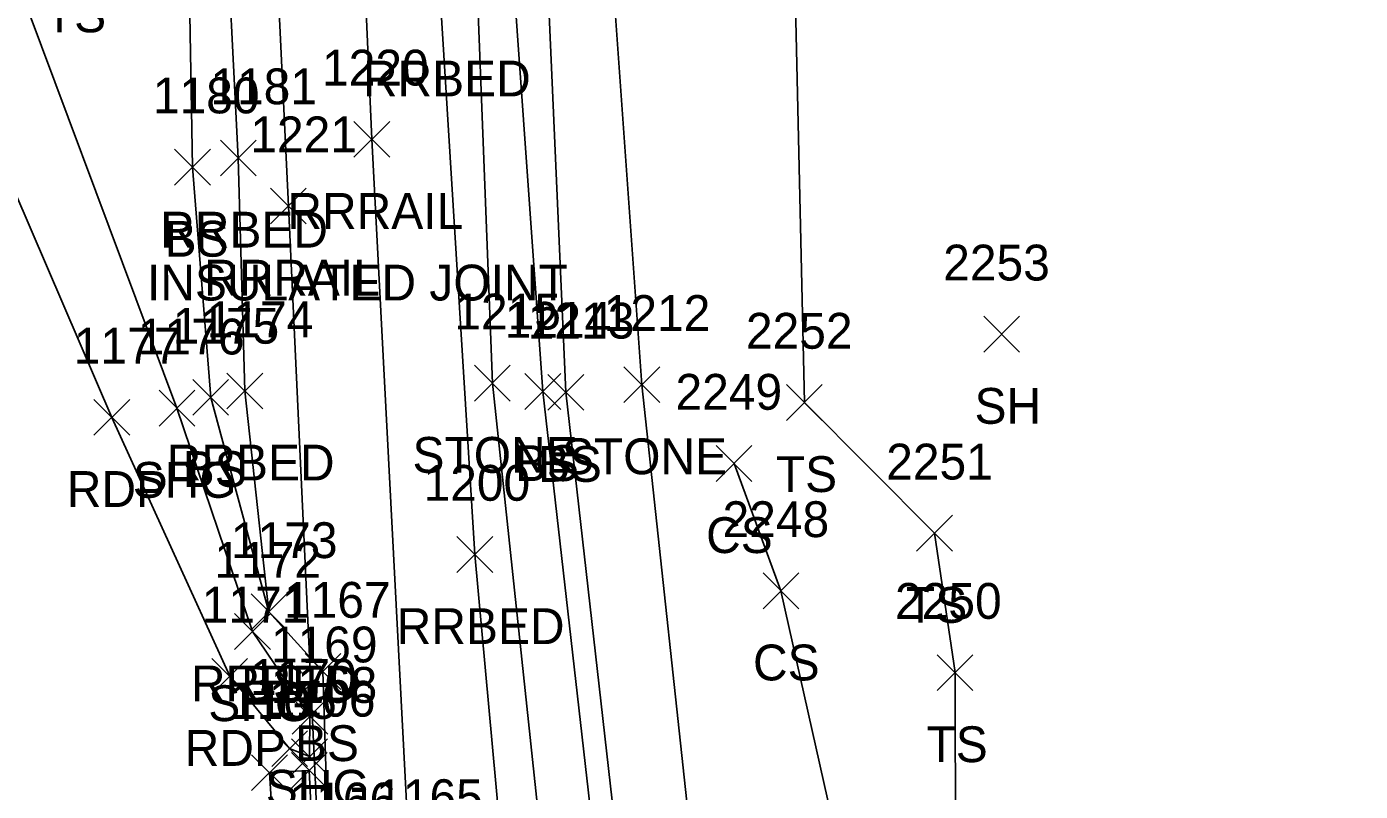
# Model space of a CAD drawing. Extents: x 1769141 to 1770817, y 735471 to 742405.
# Drawn here: x 1770154.8 to 1770229.2, y 740935.3 to 740978 of the extents above; entities that cross this region are included whole.
import ezdxf

# ---------------------------------------------------------------- set-up
doc = ezdxf.new("R2010")
doc.units = 0
for name, color, linetype in [('L_A', 7, 'Continuous'), ('L_I', 7, 'Continuous'), ('L_TIC', 7, 'Continuous'), ('LASF', 7, 'Continuous'), ('LELB', 7, 'Continuous'), ('LS', 7, 'Continuous'), ('P_A', 7, 'Continuous'), ('P_I', 7, 'Continuous'), ('P_TIC', 7, 'Continuous'), ('PET', 7, 'Continuous'), ('PSU', 7, 'Continuous'), ('R_A', 7, 'Continuous'), ('R_C', 7, 'Continuous'), ('R_I', 7, 'Continuous'), ('R_TIC', 7, 'Continuous'), ('RR', 7, 'Continuous'), ('RRB', 7, 'Continuous')]:
    doc.layers.add(name, color=color, linetype=linetype)

msp = doc.modelspace()

# ---------------------------------------------------------------- linework, layer by layer
at = {"layer": 'L_TIC'}
for points in [[(1770163.098, 740969.155), (1770165.098, 740971.155)], [(1770165.098, 740969.155), (1770163.098, 740971.155)], [(1770208.233, 740959.825), (1770210.233, 740961.825)], [(1770210.233, 740959.825), (1770208.233, 740961.825)], [(1770179.824, 740957.089), (1770181.824, 740959.089)], [(1770181.824, 740957.089), (1770179.824, 740959.089)], [(1770188.161, 740957.008), (1770190.161, 740959.008)], [(1770190.161, 740957.008), (1770188.161, 740959.008)], [(1770164.11, 740956.298), (1770166.11, 740958.298)], [(1770166.11, 740956.298), (1770164.11, 740958.298)], [(1770182.64, 740956.629), (1770184.64, 740958.629)], [(1770184.64, 740956.629), (1770182.64, 740958.629)], [(1770183.924, 740956.584), (1770185.924, 740958.584)], [(1770185.924, 740956.584), (1770183.924, 740958.584)], [(1770197.228, 740956.016), (1770199.228, 740958.016)], [(1770199.228, 740956.016), (1770197.228, 740958.016)], [(1770193.306, 740952.609), (1770195.306, 740954.609)], [(1770195.306, 740952.609), (1770193.306, 740954.609)], [(1770204.486, 740948.715), (1770206.486, 740950.715)], [(1770206.486, 740948.715), (1770204.486, 740950.715)], [(1770195.923, 740945.499), (1770197.923, 740947.499)], [(1770197.923, 740945.499), (1770195.923, 740947.499)], [(1770167.363, 740944.327), (1770169.363, 740946.327)], [(1770169.363, 740944.327), (1770167.363, 740946.327)], [(1770170.373, 740940.995), (1770172.373, 740942.995)], [(1770172.373, 740940.995), (1770170.373, 740942.995)], [(1770205.632, 740940.936), (1770207.632, 740942.936)], [(1770207.632, 740940.936), (1770205.632, 740942.936)], [(1770167.395, 740935.351), (1770169.395, 740937.351)], [(1770169.395, 740935.351), (1770167.395, 740937.351)], [(1770169.611, 740935.475), (1770171.611, 740937.475)], [(1770171.611, 740935.475), (1770169.611, 740937.475)]]:
    msp.add_lwpolyline(points, dxfattribs=at)
at = {"layer": 'LASF'}
for points in [[(1770187.933, 740904.335), (1770186.25, 740912.517), (1770185.896, 740916.663), (1770184.8, 740920.675), (1770184.076, 740927.626), (1770180.824, 740958.089), (1770179.668, 740988.396), (1770181.485, 740987.987), (1770183.564, 740988.367), (1770187.024, 740987.971)], [(1770187.933, 740904.335), (1770192.494, 740904.26), (1770195.908, 740905.277), (1770194.933, 740916.209), (1770192.16, 740930.231), (1770189.161, 740958.008), (1770187.024, 740987.971)]]:
    msp.add_lwpolyline(points, dxfattribs=at)
at = {"layer": 'LELB'}
for points in [[(1770181.311, 740917.449), (1770179.59, 740921.475), (1770177.118, 740921.478), (1770176.513, 740930.978), (1770171.729, 740930.79), (1770171.373, 740941.995), (1770168.363, 740945.327), (1770165.11, 740957.298), (1770164.098, 740970.155), (1770163.553, 741001.041), (1770161.742, 741032.797), (1770159.725, 741061.367), (1770159.572, 741081.418), (1770161.803, 741087.488), (1770164.515, 741088.618), (1770171.551, 741089.247), (1770172.918, 741077.122), (1770176.833, 741048.502), (1770177.259, 741011.933), (1770177.974, 741001.323)], [(1770191.558, 740906.735), (1770190.424, 740913.16), (1770188.625, 740919.349), (1770188.228, 740928.375), (1770184.924, 740957.584), (1770183.564, 740988.367), (1770184.534, 741002.508), (1770184.56, 741025.112), (1770184.692, 741042.338), (1770184.347, 741072.054), (1770184.959, 741087.855), (1770183.86, 741087.602), (1770172.875, 741083.308)], [(1770202.748, 740852.913), (1770198.081, 740870.23), (1770189.013, 740895.049), (1770187.933, 740904.335), (1770187.578, 740912.346), (1770187.376, 740919.181), (1770186.633, 740920.541), (1770186.963, 740928.353), (1770183.64, 740957.629), (1770181.485, 740987.987), (1770182.217, 741002.634), (1770183.145, 741024.654), (1770182.277, 741042.266), (1770177.798, 741053.788), (1770174.941, 741071.303), (1770172.875, 741083.308)], [(1770246.421, 740860.872), (1770241.286, 740876.805), (1770234.165, 740888.347), (1770224.288, 740902.422), (1770215.42, 740910.628), (1770206.685, 740921.814), (1770206.632, 740941.936), (1770205.486, 740949.715), (1770198.228, 740957.016), (1770197.639, 740983.28), (1770195.586, 740993.523), (1770190.462, 741017.376), (1770192.785, 741047.528), (1770191.915, 741067.839)], [(1770200.611, 740929.991), (1770196.923, 740946.499), (1770194.306, 740953.609)]]:
    msp.add_lwpolyline(points, dxfattribs=at)
at = {"layer": 'LS'}
msp.add_lwpolyline([(1770175.91, 740828.532), (1770173.666, 740828.505), (1770172.741, 740849.746), (1770171.207, 740883.814), (1770169.489, 740918.486), (1770168.395, 740936.351), (1770170.611, 740936.475), (1770171.921, 740909.341), (1770173.586, 740877.315), (1770175.431, 740837.66), (1770175.91, 740828.532)], dxfattribs=at)
at = {"layer": 'P_TIC'}
for points in [[(1770162.228, 740955.694), (1770164.228, 740957.694)], [(1770164.228, 740955.694), (1770162.228, 740957.694)], [(1770158.597, 740955.183), (1770160.597, 740957.183)], [(1770160.597, 740955.183), (1770158.597, 740957.183)], [(1770166.442, 740943.226), (1770168.442, 740945.226)], [(1770168.442, 740943.226), (1770166.442, 740945.226)], [(1770165.172, 740940.73), (1770167.172, 740942.73)], [(1770167.172, 740940.73), (1770165.172, 740942.73)], [(1770169.65, 740938.505), (1770171.65, 740940.505)], [(1770171.65, 740938.505), (1770169.65, 740940.505)], [(1770168.513, 740936.69), (1770170.513, 740938.69)], [(1770170.513, 740936.69), (1770168.513, 740938.69)], [(1770169.626, 740936.246), (1770171.626, 740938.246)], [(1770171.626, 740936.246), (1770169.626, 740938.246)], [(1770169.626, 740936.246), (1770171.626, 740938.246)], [(1770171.626, 740936.246), (1770169.626, 740938.246)]]:
    msp.add_lwpolyline(points, dxfattribs=at)
at = {"layer": 'PET'}
msp.add_lwpolyline([(1770170.626, 740937.246), (1770169.513, 740937.69), (1770166.172, 740941.73), (1770159.597, 740956.183), (1770147.836, 740983.509)], dxfattribs=at)
at = {"layer": 'PSU'}
msp.add_lwpolyline([(1770170.626, 740937.246), (1770170.65, 740939.505), (1770167.442, 740944.226), (1770163.228, 740956.694), (1770152.614, 740985.038)], dxfattribs=at)
at = {"layer": 'R_TIC'}
for points in [[(1770173.1, 740970.708), (1770175.1, 740972.708)], [(1770175.1, 740970.708), (1770173.1, 740972.708)], [(1770165.65, 740969.662), (1770167.65, 740971.662)], [(1770167.65, 740969.662), (1770165.65, 740971.662)], [(1770168.445, 740966.981), (1770170.445, 740968.981)], [(1770170.445, 740966.981), (1770168.445, 740968.981)], [(1770166.014, 740956.66), (1770168.014, 740958.66)], [(1770168.014, 740956.66), (1770166.014, 740958.66)], [(1770178.842, 740947.528), (1770180.842, 740949.528)], [(1770180.842, 740947.528), (1770178.842, 740949.528)], [(1770167.363, 740944.327), (1770169.363, 740946.327)], [(1770169.363, 740944.327), (1770167.363, 740946.327)]]:
    msp.add_lwpolyline(points, dxfattribs=at)
at = {"layer": 'RR'}
for points in [[(1770197.753, 740390.494), (1770195.855, 740429.491), (1770193.917, 740468.481), (1770191.987, 740507.454), (1770190.016, 740546.417), (1770188.175, 740585.45), (1770186.345, 740624.52), (1770184.351, 740663.534), (1770182.414, 740702.58), (1770181.022, 740730.449), (1770179.246, 740766.268), (1770177.157, 740810.299), (1770173.744, 740877.111), (1770171.322, 740927.707), (1770169.445, 740967.981), (1770167.613, 741006.359), (1770166.537, 741027.4), (1770165.653, 741046.208), (1770163.837, 741084.651), (1770161.662, 741123.764), (1770160.41, 741153.194), (1770158.416, 741192.158), (1770156.873, 741228.018)], [(1770203.658, 740370.746), (1770201.768, 740409.672), (1770199.783, 740448.72), (1770197.896, 740487.783), (1770195.957, 740526.733), (1770194.091, 740565.766), (1770192.139, 740604.842), (1770190.284, 740643.849), (1770188.287, 740682.87), (1770186.409, 740721.831), (1770184.146, 740769.997), (1770182.623, 740801.289), (1770179.628, 740862.115), (1770176.856, 740918.905), (1770174.1, 740971.708), (1770172.224, 741013.506), (1770171.361, 741030.469), (1770170.329, 741051.221), (1770168.957, 741081.093), (1770166.986, 741119.982), (1770165.661, 741147.286), (1770164.69, 741163.317), (1770164.281, 741173.164), (1770162.436, 741212.293)]]:
    msp.add_lwpolyline(points, dxfattribs=at)
at = {"layer": 'RRB'}
for points in [[(1770171.551, 741089.247), (1770171.802, 741075.818), (1770174.339, 741048.396), (1770176.174, 741011.52), (1770177.974, 741001.323), (1770177.958, 740979.099), (1770179.842, 740948.528), (1770182.395, 740920.735)], [(1770168.363, 740945.327), (1770167.014, 740957.66), (1770166.65, 740970.662), (1770165.111, 741000.961), (1770162.752, 741033.641), (1770161.012, 741061.171), (1770159.572, 741081.418)]]:
    msp.add_lwpolyline(points, dxfattribs=at)

# ---------------------------------------------------------------- texts
at = {"layer": 'L_A'}
for s, p in [('TS', (1770155.862, 740977.68)), ('BS', (1770162.539, 740965.155)), ('SH', (1770207.721, 740955.825)), ('STONE', (1770176.368, 740953.089)), ('BS', (1770182.081, 740952.629)), ('BS', (1770183.365, 740952.584)), ('STONE', (1770184.704, 740953.008)), ('BS', (1770163.551, 740952.298)), ('TS', (1770196.637, 740952.016)), ('CS', (1770192.747, 740948.609)), ('TS', (1770203.896, 740944.715)), ('CS', (1770195.364, 740941.499)), ('BS', (1770166.804, 740940.327)), ('BS', (1770169.814, 740936.995)), ('TS', (1770205.041, 740936.936))]:
    msp.add_text(s, height=2, dxfattribs=at).set_placement(p)
at = {"layer": 'L_I'}
for s, p in [('1180', (1770161.886, 740973.155)), ('2253', (1770205.973, 740963.825)), ('1215', (1770178.698, 740961.089)), ('1214', (1770181.514, 740960.629)), ('1212', (1770187.035, 740961.008)), ('1175', (1770162.984, 740960.298)), ('1213', (1770182.798, 740960.584)), ('2252', (1770194.968, 740960.016)), ('2249', (1770191.039, 740956.609)), ('2251', (1770202.793, 740952.715)), ('2248', (1770193.663, 740949.499)), ('1173', (1770166.237, 740948.327)), ('1167', (1770169.2, 740944.995)), ('2250', (1770203.286, 740944.936)), ('1105', (1770166.19, 740939.351)), ('1106', (1770168.351, 740939.475)), ('1165', (1770174.34, 740933.978)), ('1166', (1770169.501, 740933.79))]:
    msp.add_text(s, height=2, dxfattribs=at).set_placement(p)
at = {"layer": 'P_A'}
for s, p in [('SHG', (1770160.763, 740951.694)), ('RDP', (1770157.085, 740951.183)), ('SHG', (1770164.977, 740939.226)), ('RDP', (1770163.66, 740936.73)), ('SHG', (1770168.186, 740934.505))]:
    msp.add_text(s, height=2, dxfattribs=at).set_placement(p)
at = {"layer": 'P_I'}
for s, p in [('1177', (1770157.471, 740959.183)), ('1176', (1770161.047, 740959.694)), ('1172', (1770165.316, 740947.226)), ('1171', (1770164.613, 740944.73)), ('1169', (1770168.47, 740942.505)), ('1170', (1770167.301, 740940.69)), ('1168', (1770168.453, 740940.246)), ('1168', (1770168.453, 740940.246))]:
    msp.add_text(s, height=2, dxfattribs=at).set_placement(p)
at = {"layer": 'R_A'}
for s, p in [('RRBED', (1770173.603, 740974.099)), ('RRRAIL', (1770169.391, 740966.708)), ('RRBED', (1770162.295, 740965.662)), ('RRRAIL', (1770164.737, 740962.981)), ('RRBED', (1770162.659, 740952.66)), ('RRBED', (1770175.488, 740943.528)), ('RRBED', (1770164.008, 740940.327))]:
    msp.add_text(s, height=2, dxfattribs=at).set_placement(p)
at = {"layer": 'R_C'}
msp.add_text('INSULATED JOINT', height=2, dxfattribs=at).set_placement((1770161.557, 740962.708))
at = {"layer": 'R_I'}
for s, p in [('1220', (1770171.32, 740974.708)), ('1181', (1770165.091, 740973.662)), ('1221', (1770167.32, 740970.981)), ('1174', (1770164.888, 740960.66)), ('1200', (1770176.984, 740951.528)), ('1173', (1770166.237, 740948.327))]:
    msp.add_text(s, height=2, dxfattribs=at).set_placement(p)

doc.saveas('drawing.dxf')
